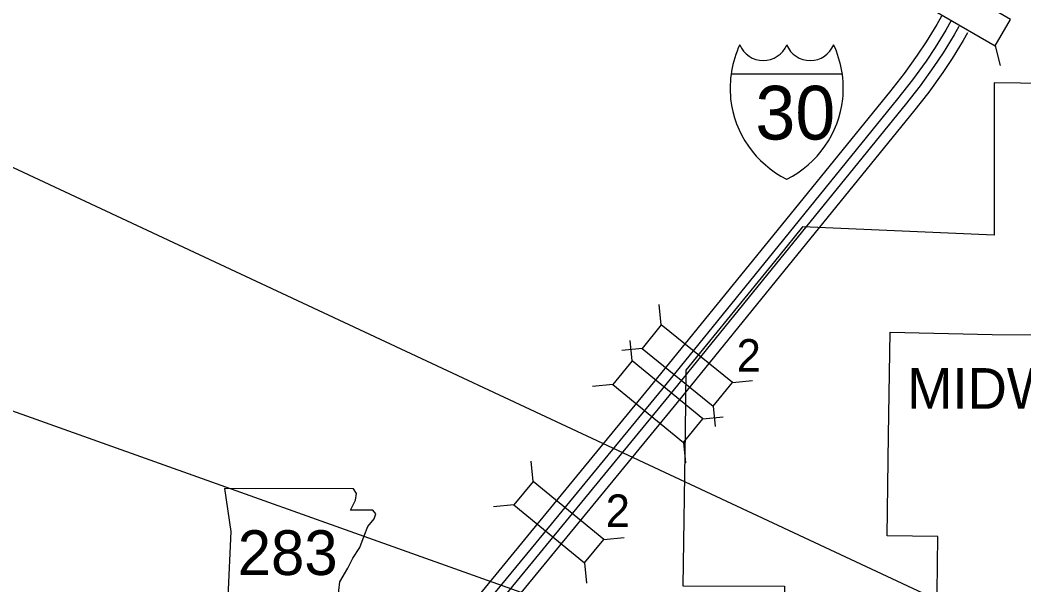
# Model space of a CAD drawing. Extents: x 1373862 to 1377080, y 1164775 to 1170415.
# Drawn here: x 1374357.1 to 1374487.3, y 1170077.8 to 1170151.1 of the extents above; entities that cross this region are included whole.
import ezdxf

# ---------------------------------------------------------------- set-up
doc = ezdxf.new("R2010")
doc.units = 0
doc.layers.add('1', color=7, linetype='Continuous')
doc.layers.add('Default', color=7, linetype='Continuous')

msp = doc.modelspace()

# ---------------------------------------------------------------- linework, layer by layer
at = {"layer": '1'}
for p in [(1374155.09, 1170226.04), (1374172.84, 1170165.77)]:
    msp.add_line(p, (1374640.76, 1169998.76), dxfattribs=at)
at = {"layer": 'Default'}
for p, q in [((1374483.59, 1170147.75), (1374484.26, 1170145.19)), ((1374449.34, 1170144.11), (1374463.76, 1170144.11)), ((1374440.28, 1170111.53), (1374440.01, 1170114.16)), ((1374436.5, 1170106.86), (1374436.24, 1170109.49)), ((1374437.79, 1170108.46), (1374435.16, 1170108.19)), ((1374433.98, 1170103.8), (1374431.36, 1170103.55)), ((1374449.51, 1170104.05), (1374452.13, 1170104.32)), ((1374447.01, 1170100.97), (1374447.28, 1170098.35)), ((1374445.68, 1170099.33), (1374448.31, 1170099.59)), ((1374443.17, 1170096.27), (1374443.42, 1170093.64)), ((1374423.66, 1170091.22), (1374423.4, 1170093.85)), ((1374421.14, 1170088.16), (1374418.52, 1170087.91)), ((1374432.84, 1170083.69), (1374435.47, 1170083.95)), ((1374430.33, 1170080.63), (1374430.58, 1170078))]:
    msp.add_line(p, q, dxfattribs=at)
for points in [[(1374485.59, 1170151.17), (1374475.33, 1170157.16), (1374473.33, 1170153.74), (1374483.59, 1170147.75)], [(1374449.51, 1170104.05), (1374440.28, 1170111.53), (1374437.79, 1170108.46), (1374447.01, 1170100.97)], [(1374433.98, 1170103.8), (1374443.17, 1170096.27), (1374445.68, 1170099.33), (1374436.5, 1170106.86)], [(1374432.84, 1170083.69), (1374423.66, 1170091.22), (1374421.14, 1170088.16), (1374430.33, 1170080.63)], [(1374383.58, 1170090.28), (1374384.42, 1170084.7), (1374384.05, 1170076.23), (1374384.79, 1170075.76), (1374386.19, 1170075.76), (1374386.19, 1170072.79), (1374397.91, 1170072.79), (1374398.47, 1170074), (1374398.29, 1170075.95), (1374398.57, 1170078.18), (1374399.59, 1170079.95), (1374400.24, 1170081.25), (1374401.17, 1170082.65), (1374401.73, 1170084.14), (1374402.19, 1170085.35), (1374403.03, 1170086.37), (1374403.22, 1170087.02), (1374402.85, 1170087.49), (1374399.96, 1170087.49), (1374400.61, 1170088.79), (1374400.71, 1170089.63), (1374400.32, 1170090.27)]]:
    msp.add_lwpolyline(points, close=True, dxfattribs=at)
for points in [[(1374476.64, 1170151.58), (1374476.02, 1170150.51), (1374474.65, 1170148.28), (1374473.5, 1170146.56), (1374471.79, 1170144.15), (1374469.88, 1170141.75), (1374453.76, 1170121.89), (1374439.24, 1170103.99), (1374422.93, 1170084.13)], [(1374477.91, 1170151.02), (1374477.21, 1170149.8), (1374475.81, 1170147.54), (1374474.63, 1170145.78), (1374472.89, 1170143.32), (1374470.95, 1170140.89), (1374454.83, 1170121.02), (1374440.3, 1170103.12), (1374423.99, 1170083.26)], [(1374478.9, 1170150.24), (1374478.28, 1170149.16), (1374476.86, 1170146.86), (1374475.66, 1170145.07), (1374473.89, 1170142.57), (1374471.92, 1170140.1), (1374455.8, 1170120.24), (1374441.27, 1170102.33), (1374424.96, 1170082.46)], [(1374480.02, 1170149.43), (1374479.46, 1170148.46), (1374478.02, 1170146.12), (1374476.8, 1170144.29), (1374474.99, 1170141.74), (1374472.99, 1170139.24), (1374456.87, 1170119.37), (1374442.34, 1170101.46), (1374426.02, 1170081.59)], [(1374497.26, 1170149.23), (1374497.12, 1170142.76), (1374483.49, 1170142.96), (1374483.48, 1170136.36), (1374483.47, 1170123.18), (1374458.59, 1170124.26)], [(1374458.59, 1170124.26), (1374455.51, 1170120.47), (1374443.46, 1170105.67)], [(1374476.06, 1170076.79), (1374476.17, 1170084.07), (1374469.57, 1170084.16), (1374469.77, 1170097.2), (1374469.96, 1170110.6), (1374483.2, 1170110.29), (1374496.4, 1170110.18), (1374496.66, 1170122.9), (1374510.03, 1170122.73)], [(1374443.46, 1170105.67), (1374443.37, 1170097.72), (1374443.07, 1170077.64), (1374456.27, 1170077.61), (1374456.19, 1170071.96), (1374456.5, 1170071.63), (1374456.65, 1170071.42), (1374456.82, 1170071.13), (1374456.91, 1170070.89), (1374457.26, 1170070.89)], [(1374422.93, 1170084.13), (1374411.17, 1170069.8)], [(1374423.99, 1170083.26), (1374412.24, 1170068.95)], [(1374424.96, 1170082.46), (1374413.23, 1170068.17)], [(1374426.02, 1170081.59), (1374414.3, 1170067.32)]]:
    msp.add_lwpolyline(points, dxfattribs=at)
for centre, radius, start, end in [((1374462.74, 1170142.23), 13.53, 155.2204, 185.7928), ((1374453.51, 1170149.14), 3.3, 202.1459, 337.3414), ((1374459.59, 1170149.14), 3.3, 202.6586, 337.8541), ((1374450.36, 1170142.23), 13.53, 354.2072, 24.7796), ((1374462.49, 1170142.34), 13.3, 186.3923, 243.4571), ((1374450.61, 1170142.34), 13.3, 296.5429, 353.6077)]:
    msp.add_arc(centre, radius, start, end, dxfattribs=at)

# ---------------------------------------------------------------- texts
for s, height, p in [('30', 6.97, (1374452.49, 1170135.59)), ('2', 4.22, (1374450.06, 1170105.46)), ('MIDWAY', 5.28, (1374472.18, 1170100.64)), ('2', 4.22, (1374433.07, 1170085.3)), ('283', 5.808, (1374385.32, 1170079.06))]:
    msp.add_text(s, height=height, dxfattribs=at).set_placement(p)

doc.saveas('drawing.dxf')
